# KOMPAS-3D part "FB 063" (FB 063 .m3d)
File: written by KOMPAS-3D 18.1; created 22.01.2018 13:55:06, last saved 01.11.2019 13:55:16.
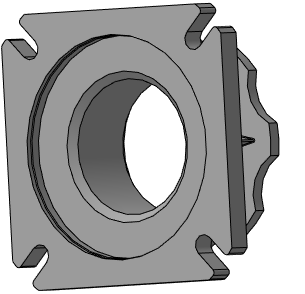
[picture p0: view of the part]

Document properties: Полное имя файла: D:\Мембранные насосы\Мембранный электропривод\А302-00.00.000 - ASTRA-302 (МЭ200)\3Д ПВХ\FB 063 .m3d

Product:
- Part/product: FB 063
    Масса: 1.71461

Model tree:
1. Операция без истории:1
2. Эскиз:1  (with: Операция без истории:1)
3. Элемент выдавливания:3  (with: Операция без истории:1)
     Расстояние 1 = 3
